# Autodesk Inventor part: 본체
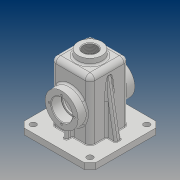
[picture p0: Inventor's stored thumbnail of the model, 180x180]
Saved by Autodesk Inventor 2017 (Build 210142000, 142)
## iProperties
Part Number: 본체
Material: 일반
Document SubType Name: Modeling
Designer: 20
Density: 1 g/cm^3
Appearance: 기본값
Author: 20
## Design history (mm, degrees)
sketch "스케치1"
  geometry: L1 (-32.5, -32.5)-(32.5, -32.5); L2 (32.5, -32.5)-(32.5, 32.5); L3 (32.5, 32.5)-(-32.5, 32.5); L4 (-32.5, 32.5)-(-32.5, -32.5); L5 (-32.5, -32.5)-(32.5, 32.5); L6 (32.5, -32.5)-(-32.5, 32.5); 1 further point
  constraints: 12 end point, 2 midpoint, 2 parallel, 1 horizontal, 1 perpendicular
  dimensions: "d0" = 65 distance of L2.end L3.end; "d1" = 65 distance of L1.end L2.end
extrude "돌출1" new body sketch "스케치1" distance "d2" = 110; taper "d3" = 0 deg
fillet "모깎기1" dims "d4" = 8
fillet "모깎기2" dims "d5" = 8
feature "쉘1" dims "d6" = 5
sketch "스케치2"
  geometry: L1 (60, 60)-(-60, 60); L2 (-60, 60)-(-60, -60); L3 (-60, -60)-(60, -60); L4 (60, -60)-(60, 60); L5 (60, 60)-(-60, -60); L6 (-60, 60)-(60, -60); L7 (24.5, -27.5)-(-24.5, -27.5) reference; L8 (-27.5, -24.5)-(-27.5, 24.5) reference; L9 (-24.5, 27.5)-(24.5, 27.5) reference; L10 (27.5, 24.5)-(27.5, -24.5) reference; A1 r 3 centre (-24.5, -24.5) between (-27.5, -24.5) and (-24.5, -27.5) reference; A2 r 3 centre (-24.5, 24.5) between (-24.5, 27.5) and (-27.5, 24.5) reference; A3 r 3 centre (24.5, 24.5) between (27.5, 24.5) and (24.5, 27.5) reference; A4 r 3 centre (24.5, -24.5) between (24.5, -27.5) and (27.5, -24.5) reference; 1 further point
  constraints: 12 end point, 2 midpoint, 2 parallel, 1 horizontal, 1 perpendicular
  dimensions: "d7" = 120 distance of L2.end L3.end; "d8" = 120 distance of L1.end L2.end
extrude "돌출2" join sketch "스케치2" distance "d9" = 10; taper "d10" = 0 deg
chamfer "모따기1" distance "d11" = 10; stored, may be unused: second distance "d12" = 2, angle "d13" = 45 deg
sketch "스케치3"
  geometry: L1 (74.5, -102)-(-25.5, -102) reference; C1 r 27.5 at (24.5, -47); 2 further points
  constraints: 1 centre point, 1 midpoint, 1 vertical alignment
  dimensions: "d14" = 55 diameter of C1; "d15" = 55 distance from line of L1 C1.centre
extrude "돌출3" join sketch "스케치3" distance "d16" = 15; taper "d17" = 0 deg
sketch "스케치4"
  geometry: L1 (-24.5, -27.5)-(24.5, -27.5) reference; L2 (-3, -27.5)-(3, -27.5); L3 (3, -27.5)-(3, -42.5); L4 (3, -42.5)-(-3, -42.5); L5 (-3, -42.5)-(-3, -27.5); 2 further points
  constraints: 8 end point, 2 parallel, 1 horizontal, 1 midpoint, 1 perpendicular, 1 point on line, 1 vertical alignment
  dimensions: "d18" = 6 distance of L3.end L4.end; "d19" = 15 distance between parallel lines of L1 L4
extrude "돌출4" join sketch "스케치4" stored distance "d20" = 15; taper "d21" = 0 deg
sketch "스케치5"
  geometry: L1 (-32.5, 102)-(-32.5, 10) reference; L2 (-32.5, 97.905)-(-48, 10); L3 (-60, 10)-(-60, 0) reference; L4 (-50, 10)-(-60, 10) reference; 1 further point
  constraints: 2 end point, 2 point on line
  dimensions: "d22" = 12 distance from line of L2.end L3; "d23" = 10 deg angle of L3 L2
feature "리브1" sketch "스케치5" dims "d24" = 1, "d25" = 10, "d26" = 0, "d27" = 0, "d28" = 1, "d29" = 1
sketch "스케치6"
  geometry: C1 r 15 at (0, 0); C2 r 27.5 at (0, 0) reference; 1 further point
  constraints: 1 centre point, 1 concentric
  dimensions: "d30" = 30 diameter of C1
extrude "돌출5" cut sketch "스케치6" distance "d31" = 128.75; taper "d32" = 0 deg
sketch "스케치7"
  geometry: C1 r 15 at (0, 0) reference; C2 r 17.5 at (0, 0); 1 further point
  constraints: 1 centre point, 1 coincident
  dimensions: "d33" = 35 diameter of C2
extrude "돌출6" cut sketch "스케치7" distance "d34" = 17; taper "d35" = 0 deg
sketch "스케치8"
  geometry: C1 r 20 at (0, 0); 1 further point
  constraints: 1 centre point, 1 coincident
  dimensions: "d36" = 40 diameter of C1
extrude "돌출7" join sketch "스케치8" distance "d37" = 10; taper "d38" = 0 deg
hole "구멍1" diameter "d41" = 22.835; stored, may be unused: countersink angle "d45" = 90 deg, drill point angle "d47" = 118 deg; dims "d39" = 10, "d40" = 10, "d42" = 50, "d43" = 4, "d44" = 2, "d46" = 30
sketch "스케치9" dims "d48" = 42
  geometry: C1 r 27.5 at (0, 0) reference; 3 further points
  constraints: 2 vertical alignment, 3 other
hole "구멍2" sketch "스케치9" at (0, 21) diameter "d49" = 3.242; stored, may be unused: countersink angle "d53" = 90 deg, drill point angle "d55" = 118 deg; dims "d50" = 8, "d51" = 4, "d52" = 2, "d54" = 10
sketch "스케치10"
  geometry: L1 (0, 0)-(0, 109.114); L2 (0, 0)-(-97.13, 0); C1 r 5 at (-47.5, 47.5)
  constraints: 4 end point, 1 centre point, 1 horizontal, 1 vertical
  dimensions: "d59" = 10 diameter of C1; "d62" = 47.5 distance from line of L1 C1.centre; "d63" = 47.5 distance from line of C1.centre L2
extrude "돌출8" cut sketch "스케치10" distance "d64" = 20.5; taper "d65" = 0 deg
feature "면 기울기1" dims angle "d72" = 5 deg
fillet "모깎기3" dims "d73" = 0.3
chamfer "모따기2" distance "d74" = 1; stored, may be unused: second distance "d75" = 2, angle "d76" = 45 deg
fillet "모깎기4" dims "d77" = 3
fillet "모깎기5" dims "d78" = 3
fillet "모깎기6" dims "d79" = 3
fillet "모깎기7" dims "d80" = 3
fillet "모깎기8" dims "d81" = 1
fillet "모깎기9" dims "d82" = 3
fillet "모깎기10" dims "d83" = 3
node "솔리드1"
mirror "미러1"
mirror "미러2"
mirror "미러3"
pattern_circular "원형 패턴1" dims angle "d57" = 360 deg
mirror "미러4"
pattern_linear "직사각형 패턴1" dims "d68" = 95, "d71" = 95
